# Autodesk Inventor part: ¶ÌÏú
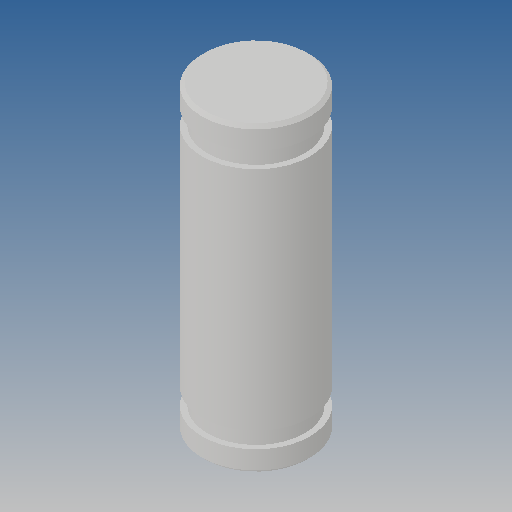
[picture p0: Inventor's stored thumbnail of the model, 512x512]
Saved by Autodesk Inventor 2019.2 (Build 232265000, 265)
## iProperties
Created: 2013-07
Part Number: ¶ÌÏú
Material: Ogólny
Document SubType Name: Modeling
Designer: CADENGINEERING4
Density: 1 g/cm^3
Appearance: Domyślna
Author: CADENGINEERING4
Revision Number: ÈÎºÎ
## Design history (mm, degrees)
feature "CALC80-¶ÌÏú.bak-1-solid1"
node "Bryła1"
